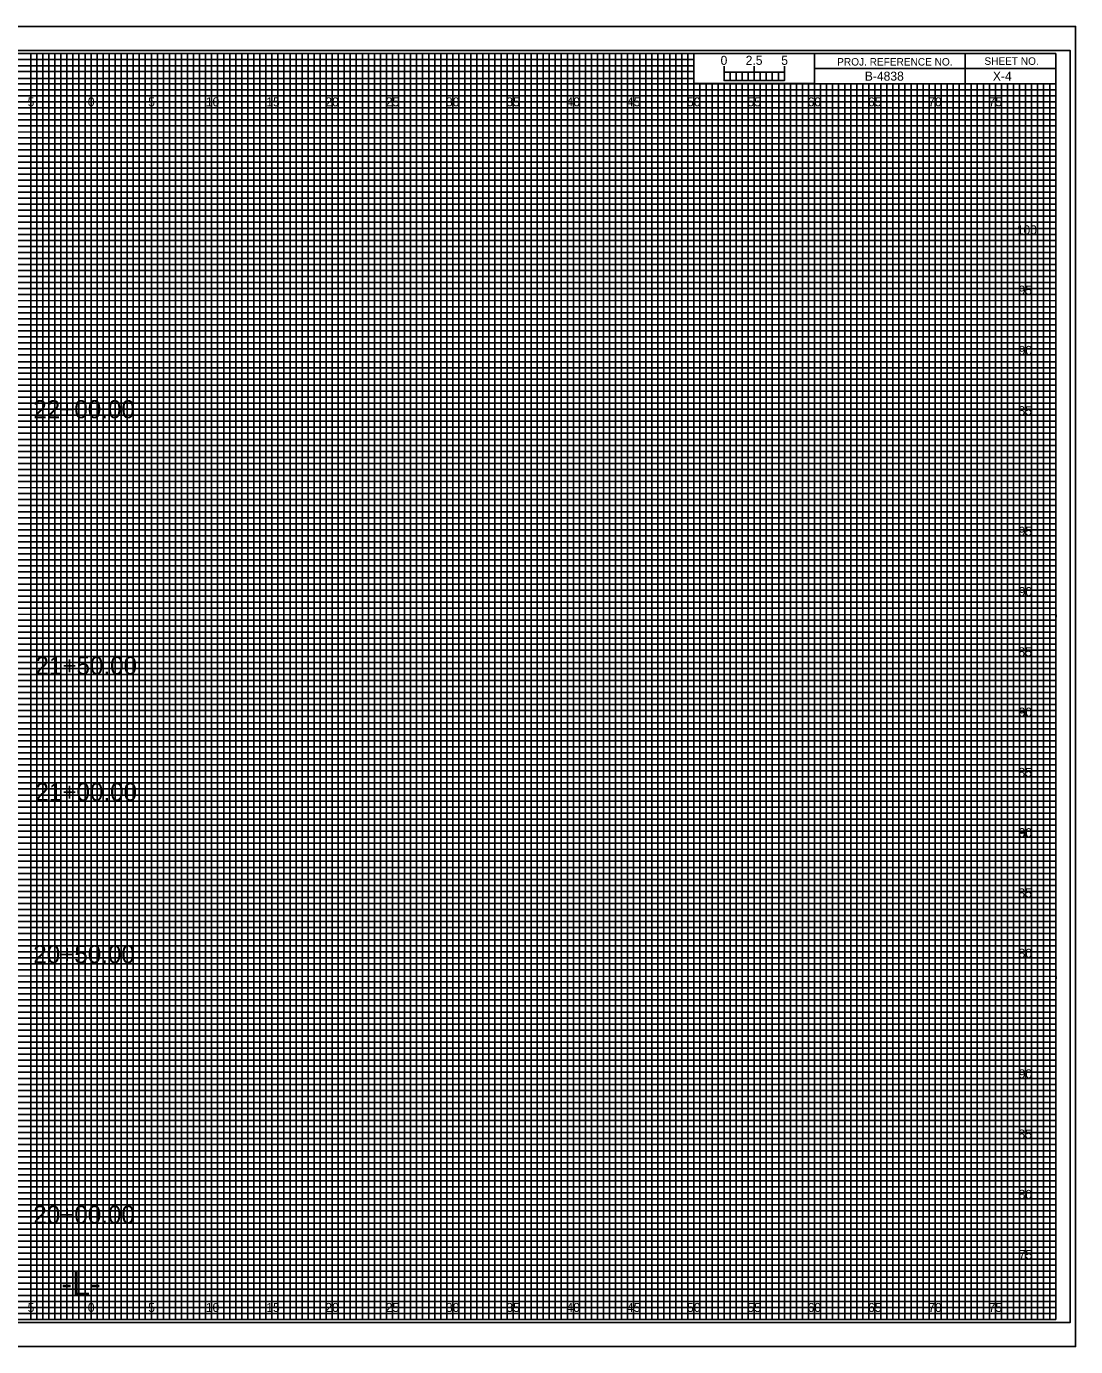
# Model space of a CAD drawing. Extents: x -7 to 182, y -2 to 1647.
# Drawn here: x 74.6 to 161.7, y 217.7 to 327.2 of the extents above; entities that cross this region are included whole.
import ezdxf

# ---------------------------------------------------------------- set-up
doc = ezdxf.new("R2010")
doc.units = 0
for name, color, linetype in [('Exist CMT Pavement', 7, 'Continuous'), ('Exist Cross Section Cell', 7, 'Continuous'), ('Exist XS Ground Line', 7, 'Continuous'), ('Prop CMT Pvmt Course 1', 7, 'Continuous'), ('Prop CMT Pvmt Course 2', 7, 'Continuous'), ('Prop CMT Pvmt Course 2 Wedge', 7, 'Continuous'), ('Prop CMT Pvmt Course 3', 7, 'Continuous'), ('Prop CMT Pvmt Surface', 7, 'Continuous'), ('Prop CMT Pvmt Surface Shoulder', 7, 'Continuous'), ('Prop CMT Pvmt Wedge Surface 1', 7, 'Continuous'), ('Prop CMT Pvmt Wedge Surface 2', 7, 'Continuous'), ('Prop CMT Pvmt Wedge Surface 3', 7, 'Continuous'), ('Prop CMT Shld Paved Course 1', 7, 'Continuous'), ('Prop CMT Shld Paved Course 2', 7, 'Continuous'), ('Prop CMT Shld Paved Course 3', 7, 'Continuous'), ('Prop CMT Slope Grass', 7, 'Continuous'), ('Prop CMT Subgrade Earthwork', 7, 'Continuous')]:
    doc.layers.add(name, color=color, linetype=linetype)

msp = doc.modelspace()

# ---------------------------------------------------------------- linework, layer by layer
at = {"layer": 'Exist XS Ground Line'}
for p, q in [((75, 325), (70, 325)), ((75, 220), (75, 325)), ((85, 325), (80, 325)), ((80, 325), (80, 220)), ((85, 220), (85, 325)), ((95, 325), (90, 325)), ((90, 325), (90, 220)), ((95, 220), (95, 325)), ((105, 325), (100, 325)), ((100, 325), (100, 220)), ((105, 220), (105, 325)), ((115, 325), (110, 325)), ((110, 325), (110, 220)), ((115, 220), (115, 325)), ((125, 325), (120, 325)), ((120, 325), (120, 220)), ((125, 220), (125, 325)), ((130, 325), (130, 220)), ((135, 220), (135, 322.5)), ((145, 322.5), (140, 322.5)), ((140, 322.5), (140, 220)), ((145, 220), (145, 322.5)), ((155, 322.5), (150, 322.5)), ((150, 322.5), (150, 220)), ((155, 220), (155, 322.5)), ((80, 220), (75, 220)), ((90, 220), (85, 220)), ((100, 220), (95, 220)), ((110, 220), (105, 220)), ((120, 220), (115, 220)), ((130, 220), (125, 220)), ((140, 220), (135, 220)), ((150, 220), (145, 220)), ((160, 220), (155, 220)), ((160, 220), (160, 220))]:
    msp.add_line(p, q, dxfattribs=at)
for points in [[(0, 320), (160, 320), (160, 315), (0, 315)], [(0, 310), (160, 310), (160, 305), (0, 305)], [(0, 300), (160, 300), (160, 295), (0, 295)], [(0, 290), (160, 290), (160, 285), (0, 285)], [(0, 280), (160, 280), (160, 275), (0, 275)], [(0, 270), (160, 270), (160, 265), (0, 265)], [(0, 260), (160, 260), (160, 255), (0, 255)], [(0, 250), (160, 250), (160, 245), (0, 245)], [(0, 240), (160, 240), (160, 235), (0, 235)], [(0, 230), (160, 230), (160, 225), (0, 225)]]:
    msp.add_lwpolyline(points, dxfattribs=at)
at = {"layer": 'Prop CMT Pvmt Course 2'}
for p, q in [((132.5, 322.75), (132.5, 323.95)), ((132.5, 323.45), (132.5, 323.95)), ((135, 322.75), (135, 323.95)), ((137.5, 322.75), (137.5, 323.95)), ((137.5, 323.45), (137.5, 323.95))]:
    msp.add_line(p, q, dxfattribs=at)
for points in [[(137.5, 323.45), (132.5, 323.45), (132.5, 322.75), (137.5, 322.75)], [(132.5, 323.45), (133, 323.45), (133, 322.75), (132.5, 322.75)], [(133.5, 323.45), (134, 323.45), (134, 322.75), (133.5, 322.75)], [(134.5, 323.45), (135, 323.45), (135, 322.75), (134.5, 322.75)], [(135.5, 323.45), (136, 323.45), (136, 322.75), (135.5, 322.75)], [(136.5, 323.45), (137, 323.45), (137, 322.75), (136.5, 322.75)]]:
    msp.add_lwpolyline(points, close=True, dxfattribs=at)
at = {"layer": 'Prop CMT Pvmt Course 3'}
msp.add_lwpolyline([(-6.7, 217.75), (161.65, 217.75), (161.65, 327.25), (-6.7, 327.25)], close=True, dxfattribs=at)
at = {"layer": 'Prop CMT Pvmt Wedge Surface 1'}
for p, q in [((0, 324.5), (130, 324.5)), ((130, 324.5), (130, 323.99)), ((130, 323.99), (0, 323.99)), ((0, 323.5), (130, 323.5)), ((130, 323.5), (130, 322.94)), ((130, 322.94), (0, 322.94)), ((0, 322), (160, 322))]:
    msp.add_line(p, q, dxfattribs=at)
for points in [[(0, 321.5), (135, 321.5), (160, 321.5), (160, 321), (0, 321)], [(0, 320.5), (160, 320.5), (160, 319.5), (0, 319.5)], [(0, 319), (160, 319), (160, 318.5), (0, 318.49)], [(0, 318), (160, 318), (160, 317), (0, 317)], [(0, 316.5), (160, 316.5), (160, 316), (0, 316)], [(0, 315.5), (160, 315.5), (160, 314.5), (0, 314.5)], [(0, 314), (160, 314), (160, 313.5), (0, 313.5)], [(0, 313), (160, 313), (160, 312), (0, 312)], [(0, 311.5), (160, 311.5), (160, 311), (0, 311)], [(0, 310.5), (160, 310.5), (160, 309.5), (0, 309.5)], [(0, 309), (160, 309), (160, 308.5), (0, 308.5)], [(0, 308), (160, 308), (160, 306.98), (160, 306.5), (160, 306), (0, 306)], [(0, 307), (160, 307), (160, 306.5), (0, 306.5)], [(0, 305.5), (160, 305.5), (160, 304.5), (0, 304.51)], [(0, 304.51), (160, 304.5), (160, 304), (0, 304)], [(0, 303.5), (160, 303.5), (160, 303), (0, 303)], [(0, 302), (160, 302), (160, 301.5), (0, 301.5)], [(0, 301), (160, 301), (160, 300.5), (0, 300.5)], [(-0.04, 299.44), (160, 299.44), (160, 298.94), (-0.04, 298.94)], [(0, 298.5), (160, 298.5), (160, 298), (0, 298)], [(0, 297), (160, 297), (160, 296.5), (0, 296.5)], [(0, 296), (160, 296), (160, 295.5), (0, 295.5)], [(0, 294.5), (160, 294.5), (160, 294), (0, 294)], [(0, 293.5), (160, 293.5), (160, 293), (0, 293)], [(0, 292), (160, 292), (160, 291.5), (0, 291.5)], [(0, 291), (160, 291), (160, 290.5), (0, 290.5)], [(0, 289.5), (160, 289.5), (160, 288.99), (0, 289)], [(0, 288.5), (160, 288.5), (160, 288), (0, 288)], [(0, 287), (160, 287), (160, 286.5), (0, 286.5)], [(0, 286), (160, 286), (160, 285.5), (0, 285.5)], [(0, 284.5), (160, 284.5), (160, 284), (0, 284)], [(0, 283.5), (160, 283.5), (160, 283), (0, 283)], [(0, 282), (160, 282), (160, 281.5), (0, 281.5)], [(0, 281), (160, 281), (160, 280.5), (0, 280.5)], [(0, 279.5), (160, 279.5), (160, 279), (0, 279)], [(0, 278.5), (160.03, 278.45), (160, 278), (0, 278)], [(0, 277), (160, 277), (160, 276.5), (0, 276.5)], [(0, 276), (160, 276), (160, 275.5), (0, 275.5)], [(0, 274.5), (160, 274.5), (160, 274), (0, 274)], [(0, 273.5), (160, 273.5), (160, 273), (0, 273)], [(0, 272), (160, 272), (160, 271.5), (0, 271.5)], [(0, 271), (160, 271), (160, 270.5), (0, 270.5)], [(0, 269.5), (160, 269.5), (160, 269), (0, 269)], [(0, 268.5), (160, 268.5), (160, 268), (0, 268)], [(0, 267), (160, 267), (160, 266.5), (0, 266.5)], [(0, 266), (160, 266), (160, 265.5), (0, 265.5)], [(0, 264.5), (160, 264.5), (160, 264), (0, 264)], [(0, 263.5), (160, 263.5), (160, 263), (0, 263)], [(0, 262), (160, 262), (160, 261.5), (0, 261.5)], [(0, 261), (160, 261), (160, 260.5), (0, 260.5)], [(0, 259.5), (160, 259.5), (160, 258.99), (0, 259)], [(0, 258.5), (160, 258.5), (160, 258), (0, 258)], [(0, 257), (160, 257), (160, 256.5), (0, 256.5)], [(0, 256), (160, 256), (160, 255.5), (0, 255.5)], [(0, 254.5), (160, 254.5), (160, 254), (0, 254)], [(0, 253.5), (160, 253.5), (160, 253), (0, 253)], [(0, 252), (160, 252), (160, 251.5), (0, 251.5)], [(0, 251), (160, 251), (160, 250.5), (0, 250.5)], [(0, 249.5), (160, 249.5), (160, 249), (0, 249)], [(0, 248.5), (160.03, 248.46), (160, 248), (0, 248)], [(0, 247), (160, 247), (160, 246.5), (0, 246.5)], [(0, 246), (160, 246), (160, 245.5), (0, 245.5)], [(0, 244.5), (160, 244.5), (160, 244), (0, 244)], [(0, 243.5), (160, 243.5), (160, 243), (0, 243)], [(0, 242), (160, 242), (160, 241.5), (0, 241.5)], [(0, 241), (160, 241), (160, 240.5), (0, 240.5)], [(0, 239.5), (160, 239.5), (160, 239), (0, 239)], [(0, 238.5), (160, 238.5), (160, 238), (0, 238)], [(0, 237), (160, 237), (160, 236.5), (0, 236.5)], [(0, 236), (160, 236), (160, 235.5), (0, 235.5)], [(0, 234.5), (160, 234.5), (160, 234), (0, 234)], [(0, 233.5), (160, 233.5), (160, 233), (0, 233)], [(0, 232), (160, 232), (160, 231.5), (0, 231.5)], [(0, 231), (160, 231), (160, 230.5), (0, 230.5)], [(0, 229.5), (160, 229.5), (160, 229), (0, 229)], [(0, 228.5), (160, 228.5), (160, 228), (0, 228)], [(0, 227), (160, 227), (160, 226.5), (0, 226.5)], [(0, 226), (160, 226), (160, 225.5), (0, 225.5)], [(0, 224.5), (160, 224.5), (160, 224), (0, 224)], [(0, 223.5), (160, 223.5), (160, 223), (0, 223)], [(0, 222), (160, 222), (160, 221.5), (0, 221.5)], [(0, 221), (160, 221), (160, 220.5), (0, 220.5)]]:
    msp.add_lwpolyline(points, dxfattribs=at)
at = {"layer": 'Prop CMT Pvmt Wedge Surface 2'}
for p, q in [((152.5, 325), (152.5, 322.5)), ((152.5, 322.5), (152.5, 325)), ((160, 323.75), (140, 323.75)), ((140, 323.75), (140, 322.5)), ((140, 322.5), (160, 322.5))]:
    msp.add_line(p, q, dxfattribs=at)
for points in [[(160, 325), (0, 325), (0, 220), (160, 220)], [(140, 325), (130, 325), (130, 322.51), (140, 322.51)], [(160, 325), (140, 325), (140, 322.5), (160, 322.5)]]:
    msp.add_lwpolyline(points, close=True, dxfattribs=at)
at = {"layer": 'Prop CMT Pvmt Wedge Surface 3'}
for p, q in [((133.5, 322.5), (133, 322.5)), ((133, 322.5), (133, 220)), ((133.5, 220), (133.5, 322.5)), ((134.5, 322.5), (134, 322.5)), ((134, 322.5), (134, 220)), ((134.5, 220), (134.5, 322.5)), ((133, 220), (132.5, 220)), ((134, 220), (133.5, 220))]:
    msp.add_line(p, q, dxfattribs=at)
for points in [[(75, 220), (75.5, 220), (75.5, 325), (76, 325), (76, 220)], [(76, 220), (76.5, 220), (76.5, 325), (77, 325), (77, 220)], [(77.5, 220), (78, 220), (78, 325), (78.5, 325), (78.5, 220)], [(78.5, 220), (79, 220), (79, 325), (79.5, 325), (79.5, 220)], [(80, 220), (80.5, 220), (80.5, 325), (81, 325), (81, 220)], [(81, 220), (81.5, 220), (81.5, 325), (82, 325), (82, 220)], [(82.5, 220), (83, 220), (83, 325), (83.5, 325), (83.5, 220)], [(83.5, 220), (84, 220), (84, 325), (84.5, 325), (84.5, 220)], [(85, 220), (85.5, 220), (85.5, 325), (86, 325), (86, 220)], [(86, 220), (86.5, 220), (86.5, 325), (87, 325), (87, 220)], [(87.5, 220), (88, 220), (88, 325), (88.5, 325), (88.5, 220)], [(88.5, 220), (89, 220), (89, 325), (89.5, 325), (89.5, 220)], [(90, 220), (90.5, 220), (90.5, 325), (91, 325), (91, 220)], [(91, 220), (91.5, 220), (91.5, 325), (92, 325), (92, 220)], [(92.5, 220), (93, 220), (93, 325), (93.5, 325), (93.5, 220)], [(93.5, 220), (94, 220), (94, 325), (94.5, 325), (94.5, 220)], [(95, 220), (95.5, 220), (95.5, 325), (96, 325), (96, 220)], [(96, 220), (96.5, 220), (96.5, 325), (97, 325), (97, 220)], [(97.5, 220), (98, 220), (98, 325), (98.5, 325), (98.5, 220)], [(98.5, 220), (99, 220), (99, 325), (99.5, 325), (99.5, 220)], [(100, 220), (100.5, 220), (100.5, 325), (101, 325), (101, 220)], [(101, 220), (101.5, 220), (101.5, 325), (102, 325), (102, 220)], [(102.5, 220), (103, 220), (103, 325), (103.5, 325), (103.5, 220)], [(103.5, 220), (104, 220), (104, 325), (104.5, 325), (104.5, 220)], [(105, 220), (105.5, 220), (105.5, 325), (106, 325), (106, 220)], [(106, 220), (106.5, 220), (106.5, 325), (107, 325), (107, 220)], [(107.5, 220), (108, 220), (108, 325), (108.5, 325), (108.5, 220)], [(108.5, 220), (109, 220), (109, 325), (109.5, 325), (109.5, 220)], [(110, 220), (110.5, 220), (110.5, 325), (111, 325), (111, 220)], [(111, 220), (111.5, 220), (111.5, 325), (112, 325), (112, 220)], [(112.5, 220), (113, 220), (113, 325), (113.5, 325), (113.5, 220)], [(113.5, 220), (114, 220), (114, 325), (114.5, 325), (114.5, 220)], [(115, 220), (115.5, 220), (115.5, 325), (116, 325), (116, 220)], [(116, 220), (116.5, 220), (116.5, 325), (117, 325), (117, 220)], [(117.5, 220), (118, 220), (118, 325), (118.5, 325), (118.5, 220)], [(118.5, 220), (119, 220), (119, 325), (119.5, 325), (119.5, 220)], [(120, 220), (120.5, 220), (120.5, 325), (121, 325), (121, 220)], [(121, 220), (121.5, 220), (121.5, 325), (122, 325), (122, 220)], [(122.5, 220), (123, 220), (123, 325), (123.5, 325), (123.5, 220)], [(123.5, 220), (124, 220), (124, 325), (124.5, 325), (124.5, 220)], [(125, 220), (125.5, 220), (125.5, 325), (126, 325), (126, 220)], [(126, 220), (126.5, 220), (126.5, 325), (127, 325), (127, 220)], [(127.5, 220), (128, 220), (128, 325), (128.5, 325), (128.5, 220)], [(128.5, 220), (129, 220), (129, 325), (129.5, 325), (129.5, 220)], [(130, 220), (130.5, 220), (130.5, 322.5), (131.01, 322.5), (131.01, 220)], [(131, 220), (131.5, 220), (131.5, 322.5), (132, 322.5), (132, 220)], [(135, 220), (135.49, 220), (135.49, 322.5), (136, 322.5), (136, 220)], [(136, 220), (136.5, 220), (136.5, 322.5), (137.03, 322.5), (137.03, 220)], [(137.5, 220), (138, 220), (138, 322.5), (138.5, 322.5), (138.5, 220)], [(138.5, 220), (139, 220), (139, 322.5), (139.5, 322.5), (139.5, 220)], [(140, 220), (140.5, 220), (140.5, 322.5), (141, 322.5), (141, 220)], [(141, 220), (141.5, 220), (141.5, 322.5), (142, 322.5), (142, 220)], [(142.5, 220), (143, 220), (143, 322.5), (143.5, 322.5), (143.5, 220)], [(143.5, 220), (144, 220), (144, 322.5), (144.5, 322.5), (144.5, 220)], [(145, 220), (145.5, 220), (145.5, 322.5), (146, 322.5), (146, 220)], [(146, 220), (146.5, 220), (146.5, 322.5), (147, 322.5), (147, 220)], [(147.5, 220), (148, 220), (148, 322.5), (148.5, 322.5), (148.5, 220)], [(148.5, 220), (149, 220), (149, 322.5), (149.5, 322.5), (149.5, 220)], [(150, 220), (150.5, 220), (150.5, 322.5), (151, 322.5), (151, 220)], [(151, 220), (151.5, 220), (151.5, 322.5), (152, 322.5), (152, 220)], [(152.5, 220), (153, 220), (153, 322.5), (153.5, 322.5), (153.5, 220)], [(153.5, 220), (154, 220), (154, 322.5), (154.5, 322.5), (154.5, 220)], [(155, 220), (155.5, 220), (155.5, 322.5), (156, 322.5), (156, 220)], [(156, 220), (156.5, 220), (156.5, 322.5), (157, 322.5), (157, 220)], [(157.5, 220), (158, 220), (158, 322.5), (158.5, 322.5), (158.5, 220)], [(158.5, 220), (159, 220), (159, 322.5), (159.5, 322.5), (159.5, 220)]]:
    msp.add_lwpolyline(points, dxfattribs=at)
at = {"layer": 'Prop CMT Shld Paved Course 1'}
for p, q in [((75, 220), (75, 325)), ((80, 220), (80, 325)), ((85, 220), (85, 325)), ((90, 220), (90, 325)), ((95, 220), (95, 325)), ((100, 220), (100, 325)), ((105, 220), (105, 325)), ((110, 220), (110, 325)), ((115, 220), (115, 325)), ((120, 220), (120, 325)), ((125, 220), (125, 325)), ((130, 220), (130, 322.34)), ((135, 220), (135, 322.34)), ((140, 220), (140, 322.34)), ((145, 220), (145, 322.34)), ((150, 220), (150, 322.34)), ((155, 220), (155, 322.34)), ((0, 320), (160, 320)), ((0, 315), (160, 315)), ((0, 310), (160, 310)), ((0, 305), (160, 305)), ((0, 300), (160, 300)), ((0, 295), (160, 295)), ((0, 290), (160, 290)), ((0, 285), (160, 285)), ((0, 280), (160, 280)), ((0, 275), (160, 275)), ((0, 270), (160, 270)), ((0, 265), (160, 265)), ((0, 260), (160, 260)), ((0, 255), (160, 255)), ((0, 250), (160, 250)), ((0, 245), (160, 245)), ((0, 240), (160, 240)), ((0, 235), (160, 235)), ((0, 230), (160, 230)), ((0, 225), (160, 225))]:
    msp.add_line(p, q, dxfattribs=at)
at = {"layer": 'Prop CMT Shld Paved Course 2'}
for p, q in [((161.65, 327.25), (-6.7, 327.25)), ((-6.7, 217.75), (161.65, 217.75))]:
    msp.add_line(p, q, dxfattribs=at)
at = {"layer": 'Prop CMT Slope Grass'}
msp.add_lwpolyline([(-5.4, 219.75), (161.2, 219.75), (161.2, 325.25), (-5.4, 325.25)], close=True, dxfattribs=at)
at = {"layer": 'Prop CMT Subgrade Earthwork'}
for points in [[(72.5, 220), (77.5, 220), (77.5, 325), (82.5, 325), (82.5, 220), (87.5, 220), (87.5, 325), (92.5, 325), (92.5, 220), (97.5, 220), (97.5, 325), (102.5, 325), (102.5, 220), (107.5, 220), (107.5, 325), (112.5, 325), (112.5, 220), (117.5, 220), (117.5, 325), (122.5, 325), (122.5, 220), (127.5, 220), (127.5, 325), (129.97, 325), (130, 325), (130, 322.5), (132.5, 322.5), (132.5, 220), (137.5, 220), (137.5, 322.5), (142.5, 322.5), (142.5, 220), (147.5, 220), (147.5, 322.5), (152.5, 322.5), (152.5, 220), (157.5, 220), (157.5, 322.5)], [(0, 322.5), (137.5, 322.5)], [(0, 312.5), (160, 312.5), (160, 317.5), (0, 317.5)], [(0, 302.5), (160, 302.5), (160, 307.5), (0, 307.5)], [(0, 292.5), (160, 292.5), (160, 297.5), (0, 297.5)], [(0, 282.5), (160, 282.5), (160, 287.5), (0, 287.5)], [(0, 272.5), (160, 272.5), (160, 277.5), (0, 277.5)], [(0, 262.5), (160, 262.5), (160, 267.5), (0, 267.5)], [(0, 252.5), (160, 252.5), (160, 257.5), (0, 257.5)], [(0, 242.5), (160, 242.5), (160, 247.5), (0, 247.5)], [(0, 232.5), (160, 232.5), (160, 237.5), (0, 237.5)], [(0, 222.5), (160, 222.5), (160, 227.5), (0, 227.5)]]:
    msp.add_lwpolyline(points, dxfattribs=at)

# ---------------------------------------------------------------- texts
at = {"layer": 'Exist CMT Pavement'}
for s, p in [('22+00.00', (75.21, 294.75)), ('21+50.00', (75.39, 273.49)), ('21+00.00', (75.39, 263.01)), ('20+50.00', (75.21, 249.55)), ('20+00.00', (75.21, 227.95))]:
    msp.add_text(s, height=1.5, dxfattribs=at).set_placement(p)
at = {"layer": 'Exist Cross Section Cell'}
for s, p in [('5', (74.74, 320.62)), ('0', (79.73, 320.62)), ('0', (79.73, 320.62)), ('5', (84.74, 320.62)), ('10', (89.52, 320.62)), ('15', (94.53, 320.62)), ('20', (99.43, 320.62)), ('25', (104.44, 320.62)), ('30', (109.43, 320.62)), ('35', (114.44, 320.62)), ('40', (119.43, 320.62)), ('45', (124.44, 320.62)), ('50', (129.43, 320.62)), ('55', (134.44, 320.62)), ('60', (139.43, 320.62)), ('65', (144.44, 320.62)), ('70', (149.43, 320.62)), ('75', (154.44, 320.62)), ('5', (74.74, 220.62)), ('0', (79.73, 220.62)), ('0', (79.73, 220.62)), ('5', (84.74, 220.62)), ('10', (89.52, 220.62)), ('15', (94.53, 220.62)), ('20', (99.43, 220.62)), ('25', (104.44, 220.62)), ('30', (109.43, 220.62)), ('35', (114.44, 220.62)), ('40', (119.43, 220.62)), ('45', (124.44, 220.62)), ('50', (129.43, 220.62)), ('55', (134.44, 220.62)), ('60', (139.43, 220.62)), ('65', (144.44, 220.62)), ('70', (149.43, 220.62)), ('75', (154.44, 220.62))]:
    msp.add_text(s, height=0.75, dxfattribs=at).set_placement(p)
at = {"layer": 'Prop CMT Pvmt Course 1'}
msp.add_text('-L-', height=2, dxfattribs=at).set_placement((77.53, 222))
at = {"layer": 'Prop CMT Pvmt Course 2'}
msp.add_text('0', height=0.75, dxfattribs=at).set_placement((132.21, 324.06))
at = {"layer": 'Prop CMT Pvmt Course 2 Wedge'}
for s, p in [('2.5', (134.29, 324.06)), ('5', (137.24, 324.06))]:
    msp.add_text(s, height=0.75, dxfattribs=at).set_placement(p)
at = {"layer": 'Prop CMT Pvmt Surface'}
msp.add_text('X-4', height=0.75, dxfattribs=at).set_placement((154.79, 322.75))
at = {"layer": 'Prop CMT Pvmt Surface Shoulder'}
msp.add_text('B-4838', height=0.75, dxfattribs=at).set_placement((144.17, 322.75))
at = {"layer": 'Prop CMT Pvmt Wedge Surface 2'}
for s, p in [('PROJ. REFERENCE NO.', (141.88, 324)), ('SHEET NO.', (154.09, 324.06))]:
    msp.add_text(s, height=0.625, dxfattribs=at).set_placement(p)
at = {"layer": 'Prop CMT Shld Paved Course 3'}
for s, p in [('100', (156.77, 310)), ('95', (156.92, 305)), ('90', (156.93, 300)), ('85', (156.91, 295)), ('95', (156.92, 285)), ('90', (156.93, 280)), ('85', (156.91, 275)), ('80', (156.92, 270)), ('90', (156.93, 270)), ('85', (156.91, 265)), ('80', (156.92, 260)), ('90', (156.93, 260)), ('85', (156.91, 255)), ('80', (156.92, 250)), ('90', (156.93, 240)), ('85', (156.91, 235)), ('80', (156.92, 230)), ('75', (156.94, 225))]:
    msp.add_text(s, height=0.75, dxfattribs=at).set_placement(p)

doc.saveas('drawing.dxf')
